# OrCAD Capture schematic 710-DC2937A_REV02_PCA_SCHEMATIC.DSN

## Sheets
1 PAGE1: company: ANALOG DEVICES; note: DEMO BOARD BILL OF MATERIALS; note: LOW EMI LOW IQ SEPIC CONVERTER
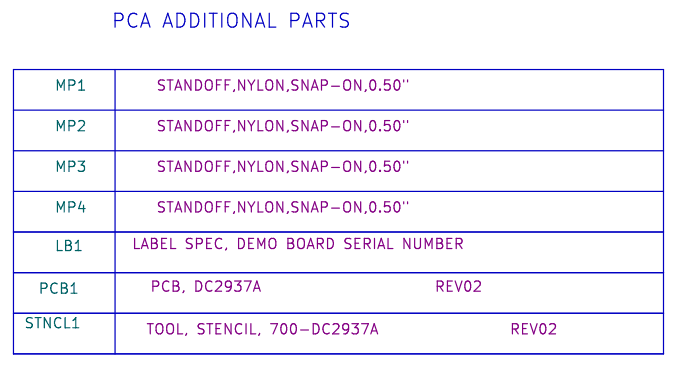
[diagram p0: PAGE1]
2 LT8357EMSE: size Custom; title: Q; note: LOW I     HIGH POWER BOOST CONVERTER
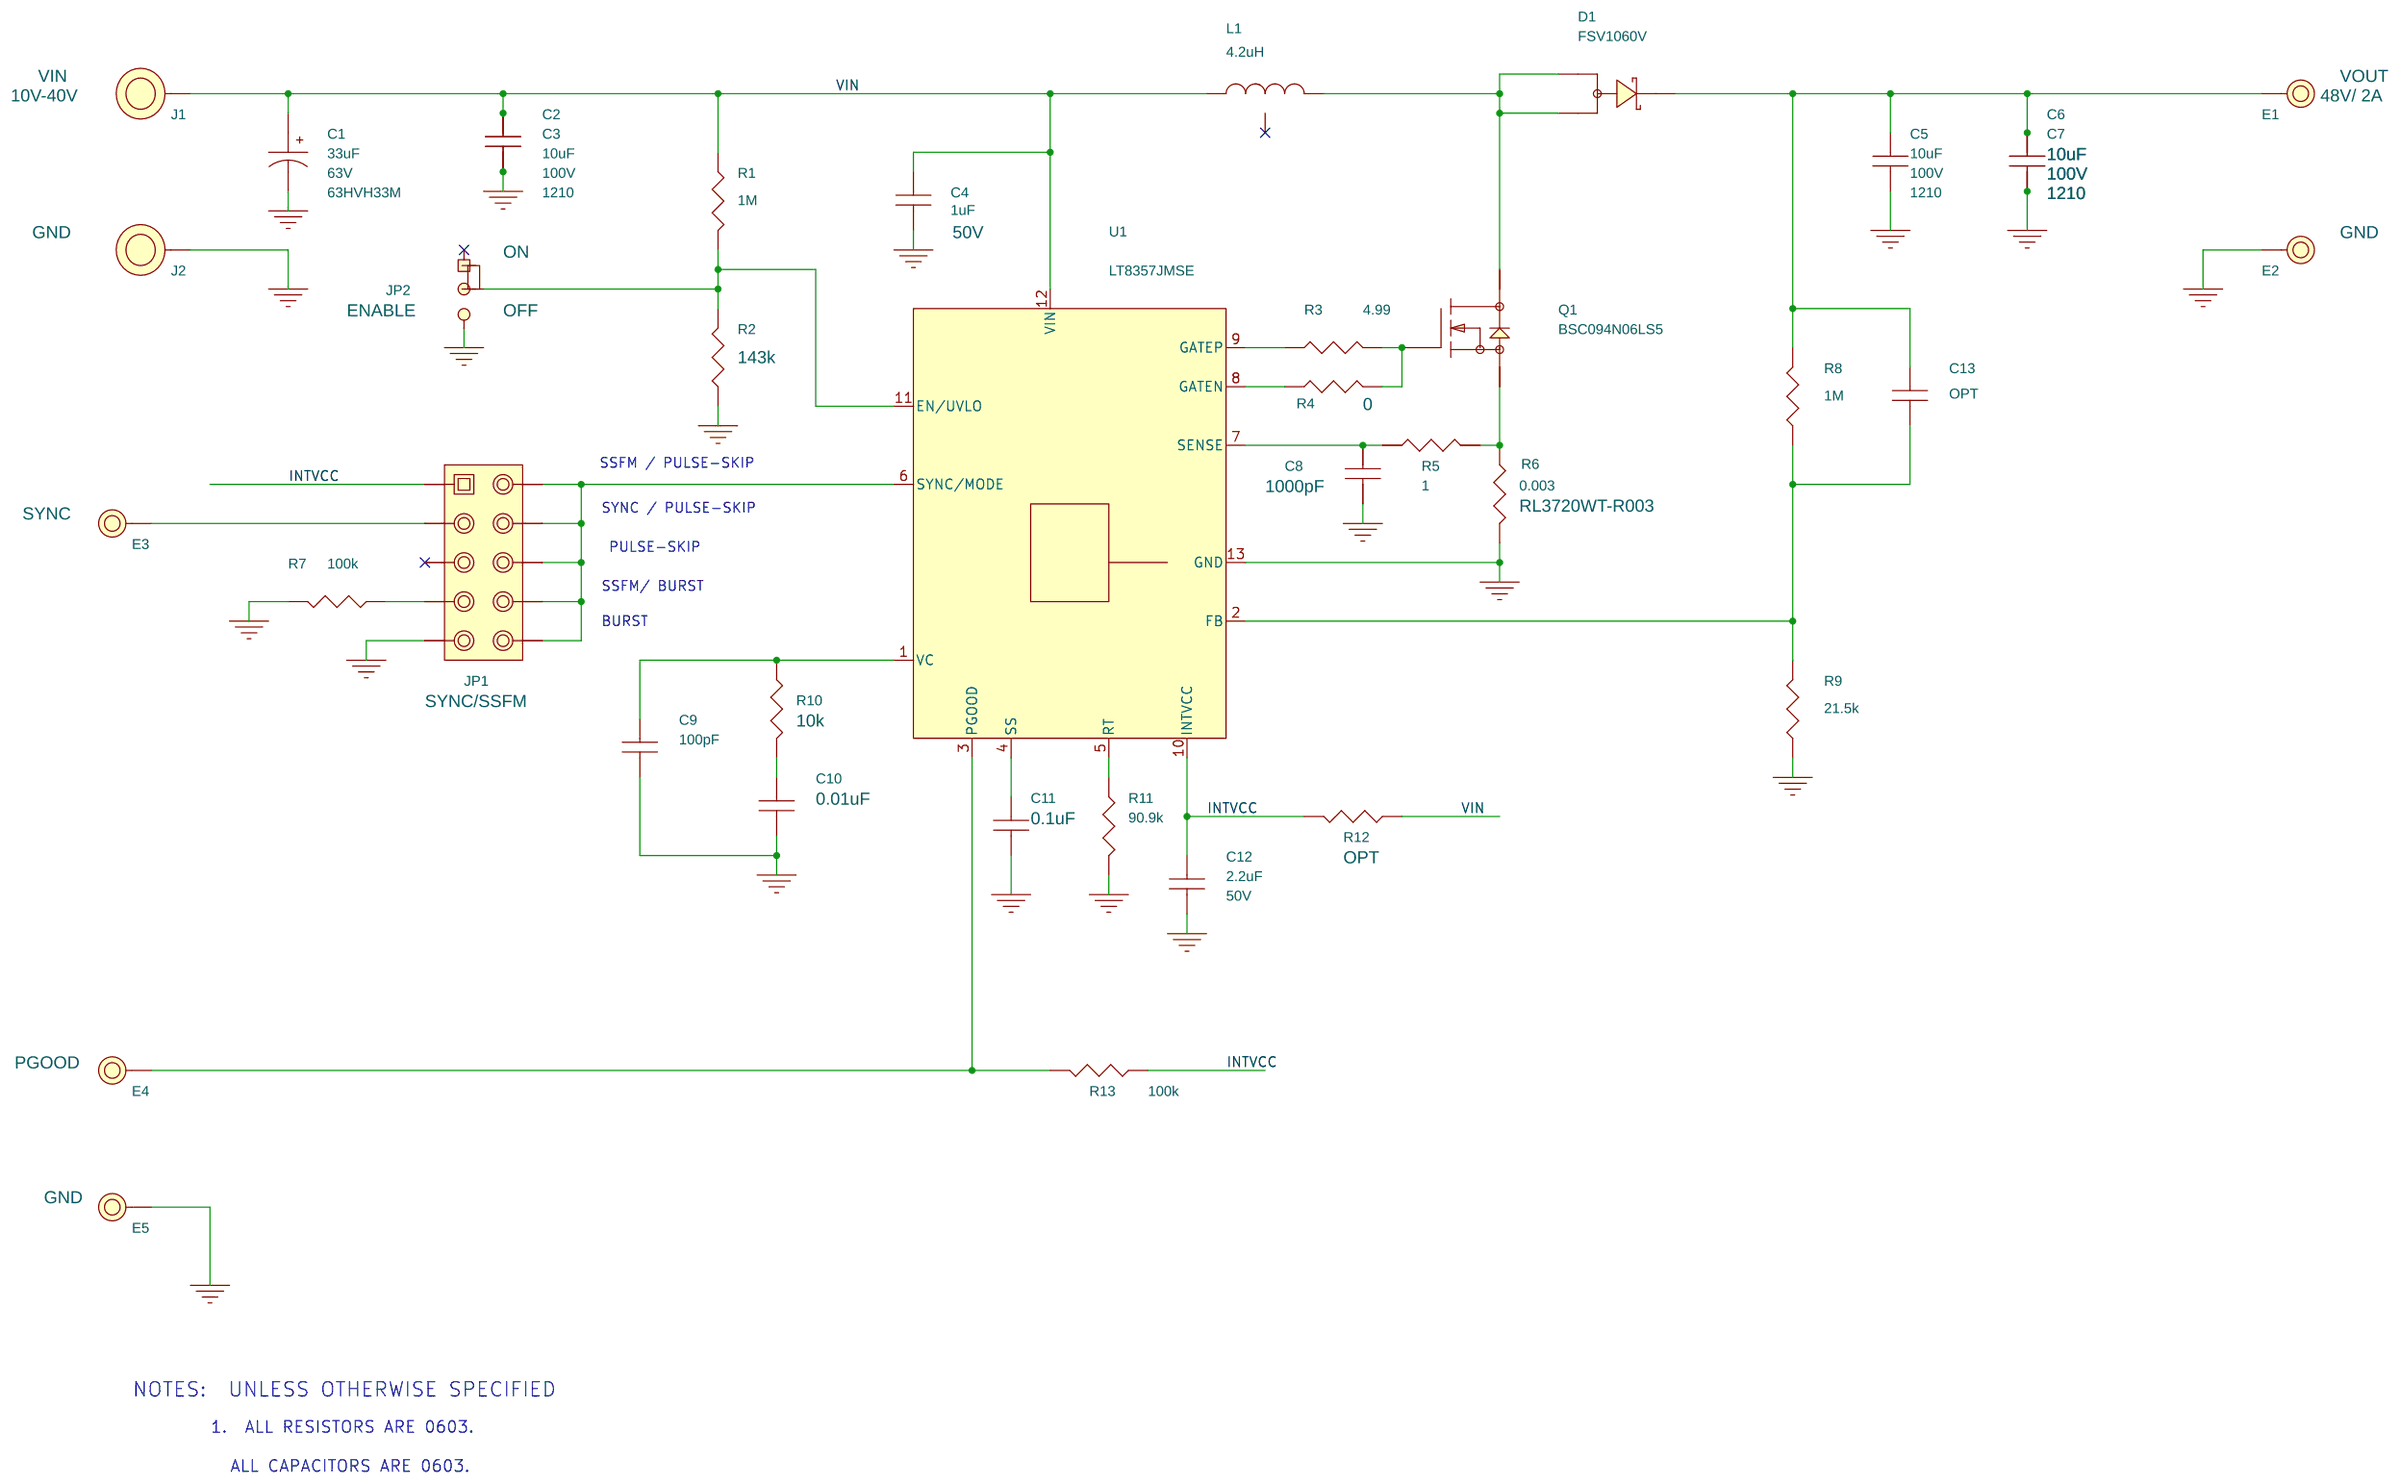
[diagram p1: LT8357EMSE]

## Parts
sheet LT8357EMSE
C1  33uF  [SUNCON_HVH_10X10.5]
C2  10uF  [CC1210N]
C3  10uF  [CC1210N]
C4  1uF  [CC0603N]
C5  10uF  [CC1210N]
C6  10uF  [CC1210N]
C7  10uF  [CC1210N]
C8  1000pF  [CC0603N]
C9  100pF  [CC0603N]
C10  0.01uF  [CC0603N]
C11  0.1uF  [CC0603N]
C12  2.2uF  [CC0603N]
C13  OPT  [CC0603N]
D1  FSV1060V  [TO-277-3N]
E1  TEST POINT  [MILLMAX2501]
E2  TEST POINT  [MILLMAX2501]
E3  TEST POINT  [MILLMAX2501]
E4  TEST POINT  [MILLMAX2501]
E5  TEST POINT  [MILLMAX2501]
J1  BANANA JACK  [KEY-575-4]
J2  BANANA JACK  [KEY-575-4]
JP1  HDR  [HD2X5-079]
JP2  HDR  [HD1X3-079]
L1  4.2uH  [WURTH-2013]
Q1  BSC094N06LS5  [INFINEON-PG-TDSON-8]
R1  1M  [CR0603N]
R2  143k  [CR0603N]
R3  4.99  [CR0603N]
R4  0  [CR0603N]
R5  1  [CR0603N]
R6  0.003  [SUSUMU-RL3720W]
R7  100k  [CR0603N]
R8  1M  [CR0603N]
R9  21.5k  [CR0603N]
R10  10k  [CR0603N]
R11  90.9k  [CR0603N]
R12  OPT  [CR0603N]
R13  100k  [CR0603N]
U1  LT8357JMSE  [LTC-MSOP-12-1666]
XJP1  SHUNT
XJP2  SHUNT
sheet PAGE1
LB1  LABEL  [895-0154_REV01]
MP1  STANDOFF  [KEYSTONE_8829-8834]
MP2  STANDOFF  [KEYSTONE_8829-8834]
MP3  STANDOFF  [KEYSTONE_8829-8834]
MP4  STANDOFF  [KEYSTONE_8829-8834]
PCB1  PCB, DC2937A
STNCL1  TOOL, STENCIL, 700-DC2937A

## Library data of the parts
C1 = CAP_P_ALT: CAP.,33uF,ALUM. ELECT.,63V,20%,10x10.5mm SMD; CLASS: DISCRETE; Dielectric Type: ALUM. ELECT.; Inventory Qty: 7004; Manufacturer: SUN ELECTRONIC INDUSTRIES CORP; Manufacturer PN: 63HVH33M; PART_NUMBER: 150-3490; Package Size: 10x10.5mm SMD; Rated Voltage: 63V; Tolerance: 20%
C2 C3 C5-C7 = CAP: CAP.,10uF,X7S,100V,10%,1210; CLASS: DISCRETE; Dielectric Type: X7S; FPLIST: CC1210N,CC1210L,CC1210M; Inventory Qty: 17323; Manufacturer: MURATA; Manufacturer PN: GRM32EC72A106KE05L; PART_NUMBER: 150-2537; Package Size: 1210; Package Type: Surface Mount, MLCC; Rated Voltage: 100V; Temperature Coefficient: X7S; Tolerance: 10%
C4 = CAP: CAP.,1uF,X7R,50V,10%,0603; CLASS: DISCRETE; Dielectric Type: X7R; FPLIST: CC0603N,CC0603L,CC0603M; Inventory Qty: 17863; Manufacturer: AVX; Manufacturer PN: 06035C105KAT2A; PART_NUMBER: 150-2333; Package Size: 0603; Rated Voltage: 50V; Tolerance: 10%
C8 = CAP: CAP.,1000pF,C0G,50V,5%,0603,AEC-Q200; CLASS: DISCRETE; Dielectric Type: C0G; FPLIST: CC0603N,CC0603L,CC0603M; Inventory Qty: 8000; Manufacturer: TDK; Manufacturer PN: CGA3E2C0G1H102J; PART_NUMBER: 150-2678; Package Size: 0603; Package Type: Surface Mount, MLCC; Rated Voltage: 50V; Temperature Coefficient: C0G, NP0; Tolerance: 5%
C9 = CAP: CAP.,100pF,C0G,50V,5%,0603,AEC-Q200; 1ST FIELD PART: TBD; CLASS: DISCRETE; Dielectric Type: C0G; FPLIST: CC0603N,CC0603L,CC0603M; Inventory Qty: 31163; Manufacturer: TDK; Manufacturer PN: CGA3E2C0G1H101J; PART_NUMBER: 150-0516; Package Size: 0603; Rated Voltage: 50V; Tolerance: 5%
C10 = CAP: CAP.,0.01uF,X7R,50V,10%,0603,AEC-Q200; 1ST FIELD PART: TBD; CLASS: DISCRETE; Dielectric Type: X7R; FPLIST: CC0603N,CC0603L,CC0603M; Inventory Qty: 1984; Manufacturer: AVX; Manufacturer PN: 06035C103K4T2A; PART_NUMBER: 150-0499; Package Size: 0603; Rated Voltage: 50V; Tolerance: 10%
C11 = CAP: CAP.,0.1uF,X7R,50V,10%,0603,AEC-Q200; 1ST FIELD PART: TBD; CLASS: DISCRETE; Dielectric Type: X7R; FPLIST: CC0603N,CC0603L,CC0603M; Inventory Qty: 20285; Manufacturer: TDK; Manufacturer PN: CGA3E2X7R1H104K; PART_NUMBER: 150-0514; Package Size: 0603; Rated Voltage: 50V; Tolerance: 10%
C12 = CAP: CAP.,2.2uF,X5R,50V,10%,0603; CLASS: DISCRETE; Dielectric Type: X5R; FPLIST: CC0603N,CC0603L,CC0603M; Inventory Qty: 35700; Manufacturer: TAIYO YUDEN; Manufacturer PN: UMK107BBJ225KA-T; PART_NUMBER: 150-0229; Package Size: 0603; Package Type: Surface Mount, MLCC; Rated Voltage: 50V; Temperature Coefficient: X5R; Tolerance: 10%
C13 = CAP: CAP., OPTION, 0603; CLASS: DISCRETE; FPLIST: CC0603N,CC0603L,CC0603M; PART_NUMBER: 150-3038; Package Size: 0603; Package Type: SMD
D1 = DIODE_SCHOTTKY_PACKAGE4: DIODE,SCHOTTKY,60V,10A,TO277-3; CLASS: DISCRETE; Inventory Qty: 0; Manufacturer: ON Semiconductor; PART_NUMBER: 210-0418; Package Size: TO-277, 3-PowerDFN; Package Type: TO277-3; Rated Voltage or Zener Voltage: 60V
E1 = TESTPOINT_.219_MILL-MAX_2501: TEST POINT,TURRET,0.094" MTG. HOLE,PCB 0.062" THK; CLASS: IO; FPLIST: MILLMAX2501,MILLMAX2501_ALT1; Inventory Qty: 609905; Manufacturer: MILL-MAX; Manufacturer PN: 2501-2-00-80-00-00-07-0; PART_NUMBER: 260-0003; Part_Field_01: VOUT; Part_Field_02: 48V/ 2A
E2 E5 = TESTPOINT_.219_MILL-MAX_2501: TEST POINT,TURRET,0.094" MTG. HOLE,PCB 0.062" THK; CLASS: IO; FPLIST: MILLMAX2501,MILLMAX2501_ALT1; Inventory Qty: 609905; Manufacturer: MILL-MAX; Manufacturer PN: 2501-2-00-80-00-00-07-0; PART_NUMBER: 260-0003; Part_Field_01: GND
E3 = TESTPOINT_.219_MILL-MAX_2501: TEST POINT,TURRET,0.094" MTG. HOLE,PCB 0.062" THK; CLASS: IO; FPLIST: MILLMAX2501,MILLMAX2501_ALT1; Inventory Qty: 609905; Manufacturer: MILL-MAX; Manufacturer PN: 2501-2-00-80-00-00-07-0; PART_NUMBER: 260-0003; Part_Field_01: SYNC
E4 = TESTPOINT_.219_MILL-MAX_2501: TEST POINT,TURRET,0.094" MTG. HOLE,PCB 0.062" THK; CLASS: IO; FPLIST: MILLMAX2501,MILLMAX2501_ALT1; Inventory Qty: 609905; Manufacturer: MILL-MAX; Manufacturer PN: 2501-2-00-80-00-00-07-0; PART_NUMBER: 260-0003; Part_Field_01: PGOOD
J1 = BANANA_KEYSTONE-575-4: CONN.,BANANA JACK,FEMALE,THT,NON-INSULATED,SWAGE,0.218"; CLASS: IO; Inventory Qty: 187327; Manufacturer: KEYSTONE; Manufacturer PN: 575-4; PART_NUMBER: 250-0428; Part_Field_01: VIN; Part_Field_02: 10V-40V
J2 = BANANA_KEYSTONE-575-4: CONN.,BANANA JACK,FEMALE,THT,NON-INSULATED,SWAGE,0.218"; CLASS: IO; Inventory Qty: 187327; Manufacturer: KEYSTONE; Manufacturer PN: 575-4; PART_NUMBER: 250-0428; Part_Field_01: GND
JP1 = HDR2X5_ALT1: CONN.,HDR,MALE,2x5,2mm,VERT,ST,THT; 1ST PART FIELD: SYNC/SSFM; CLASS: IO; Inventory Qty: 546; Manufacturer: WURTH ELEKTRONIK; Manufacturer PN: 62001021121; PART_NUMBER: 250-0679
JP2 = 1X3_D: CONN.,HDR,MALE,1x3,2mm,VERT,ST,THT,NO SUBS. ALLOWED; 1ST PART FIELD: ENABLE; 1st_Part_Field: ON; 2nd_Part_Filed: OFF; CLASS: IO; Inventory Qty: 24006; Manufacturer: Wurth Elektronik; Manufacturer PN: 62000311121; PART_NUMBER: 250-0639
L1 = IND_3PIN: IND.,4.2uH,POWER CHOKE SHEILDED,15%,24A,3.04mOHMS,2013; CLASS: DISCRETE; Inventory Qty: 700; Manufacturer: WURTH ELEKTRONIK; Manufacturer PN: 7443630420; PART_NUMBER: 200-0603; Package Size: 2013; Tolerance: 15%
Q1 = 8P_N-CH_TYPE1D: XSTR.,MOSFET,N-CHAN,60V,47A,8-pin TDSON; CLASS: DISCRETE; Inventory Qty: 4332; Manufacturer: INFINEON; Manufacturer PN: BSC094N06LS5ATMA1; PART_NUMBER: 240-0353; Package Size: 8-PowerTDFN; Package Type: 8-pin TDSON; Polarity: N-Channel; Rated Voltage: 60V
R1 R8 = RES: RES.,1M OHM,1%,1/10W,0603,AEC-Q200; CLASS: DISCRETE; FPLIST: CR0603N,CR0603L,CR0603M; Inventory Qty: 162958; Manufacturer: VISHAY; Manufacturer PN: CRCW06031M00FKEA; PART_NUMBER: 100-0335; Package Size: 0603; Rated Power: 1/10W; Temperature Coefficient: 100ppm; Tolerance: 1%
R2 = RES: RES.,143k OHMS,1%,1/10W,0603,AEC-Q200; CLASS: DISCRETE; FPLIST: CR0603N,CR0603L,CR0603M; Inventory Qty: 19828; Manufacturer: PANASONIC; Manufacturer PN: ERJ3EKF1433V; PART_NUMBER: 100-2875; Package Size: 0603; Rated Power: 1/10W; Temperature Coefficient: +/-100ppm; Tolerance: 1%
R3 = RES: RES.,4.99 OHMS,1%,1/10W,0603,AEC-Q200; CLASS: DISCRETE; FPLIST: CR0603N,CR0603L,CR0603M; Inventory Qty: 30000; Manufacturer: VISHAY; Manufacturer PN: CRCW06034R99FKEA; PART_NUMBER: 100-0521; Package Size: 0603; Rated Power: 1/10W; Temperature Coefficient: 100ppm; Tolerance: 1%
R4 = RES: RES.,0 OHM,1/10W,0603,AEC-Q200; CLASS: DISCRETE; FPLIST: CR0603N,CR0603L,CR0603M; Inventory Qty: 716853; Manufacturer: VISHAY; Manufacturer PN: CRCW06030000Z0EA; PART_NUMBER: 100-0009; Package Size: 0603; Rated Power: 1/10W
R5 = RES: RES.,1 OHM,1%,1/10W,0603,AEC-Q200; CLASS: DISCRETE; FPLIST: CR0603N,CR0603L,CR0603M; Inventory Qty: 53443; Manufacturer: NIC; Manufacturer PN: NRC06F1R00TRF; PART_NUMBER: 100-0238; Package Size: 0603; Rated Power: 1/10W; Temperature Coefficient: 100ppm/C; Tolerance: 1%
R6 = RES: RES.,0.003 OHM,1%,1W,1508 LONG-SIDE TERM; 1st_Part_Field: RL3720WT-R003; CLASS: DISCRETE; Inventory Qty: 0; Manufacturer: Susumu; Manufacturer PN: RL3720WT-R003-F; PART_NUMBER: 100-1333; Package Size: 1508 LONG-SIDE TERM; Rated Power: 1W; Temperature Coefficient: +/-350ppm; Tolerance: 1%
R7 = RES: RES.,100k OHMS,1%,1/10W,0603; CLASS: DISCRETE; FPLIST: CR0603N,CR0603L,CR0603M; Inventory Qty: 71061; Manufacturer: STACKPOLE ELECTRONICS, INC.; Manufacturer PN: RMCF0603FG100K; PART_NUMBER: 100-0112; Package Size: 0603; Rated Power: 1/10W; Tolerance: 1%
R9 = RES: RES.,21.5k OHMS,1%,1/10W,0603; CLASS: DISCRETE; FPLIST: CR0603N,CR0603L,CR0603M; Inventory Qty: 10704; Manufacturer: VISHAY; Manufacturer PN: CRCW060321K5FKEA; PART_NUMBER: 100-0107; Package Size: 0603; Rated Power: 1/10W; Temperature Coefficient: 100ppm/C; Tolerance: 1%
R10 = RES: RES.,10k OHMS,1%,1/10W,0603,AEC-Q200; 1ST FIELD PART: TBD; CLASS: DISCRETE; FPLIST: CR0603N,CR0603L,CR0603M; Inventory Qty: 161452; Manufacturer: VISHAY; Manufacturer PN: CRCW060310K0FKEA; PART_NUMBER: 100-2012; Package Size: 0603; Rated Power: 1/10W; Temperature Coefficient: +/-100ppm/C; Tolerance: 1%
R11 = RES: RES.,90.9k OHMS,1%,1/10W,0603,AEC-Q200; CLASS: DISCRETE; FPLIST: CR0603N,CR0603L,CR0603M; Inventory Qty: 76786; Manufacturer: VISHAY; Manufacturer PN: CRCW060390K9FKEA; PART_NUMBER: 100-2379; Package Size: 0603; Rated Power: 1/10W; Temperature Coefficient: 100ppm/C; Tolerance: 1%
R12 = RES: RES., OPTION, 0603; CLASS: DISCRETE; FPLIST: CR0603N,CR0603L,CR0603M; PART_NUMBER: 100-2374; Package Size: 0603
R13 = RES: RES.,100k OHMS,1%,1/10W,0603,AEC-Q200; CLASS: DISCRETE; FPLIST: CR0603N,CR0603L,CR0603M; Inventory Qty: 186177; Manufacturer: VISHAY; Manufacturer PN: CRCW0603100KFKEA; PART_NUMBER: 100-0343; Package Size: 0603; Rated Power: 1/10W; Temperature Coefficient: +/-100ppm; Tolerance: 1%
U1 = LT8357-MSE: IC,CURRENT MODE, DC/DC CONTROLLER,MSOP-12,WIDE INPUT RANGE; CLASS: IC; Inventory Qty: 0; Manufacturer: ANALOG DEVICES; Manufacturer PN: LT8357JMSE#PBF; PART_NUMBER: TMP-6534; Package Size: 12-MSOP; Package Type: MSOP-12
XJP1 = SHUNT_2MM_C: CONN.,SHUNT,FEMALE,2 POS,2mm; CLASS: IO; Inventory Qty: 67720; Manufacturer: Wurth Elektronik; Manufacturer PN: 60800213421; PART_NUMBER: 250-0485
XJP2 = SHUNT_2MM_B: CONN.,SHUNT,FEMALE,2 POS,2mm; CLASS: IO; Inventory Qty: 67720; Manufacturer: Wurth Elektronik; Manufacturer PN: 60800213421; PART_NUMBER: 250-0485
LB1 = BLANK_LABEL: LABEL SPEC, DEMO BOARD SERIAL NUMBER; Inventory Qty: 0; Manufacturer: BRADY; Manufacturer PN: THT-96-717-10; PART_NUMBER: 895-0154
MP1-MP4 = BLANK_MECHANICAL_PART: STANDOFF,NYLON,SNAP-ON,0.50"; CLASS: DISCRETE; Inventory Qty: 197954; Manufacturer: KEYSTONE; Manufacturer PN: 8833; PART_NUMBER: 763-0007
PCB1 = BLANK_PCB_PART: BOM Notes: REV02; CLASS: DISCRETE; Inventory Qty: 0; Manufacturer: EAGLE TECH. INC.; Manufacturer PN: 600-DC2937A; PART_NUMBER: 600-DC2937A
STNCL1 = BLANK_STENCIL_PART: BOM Notes: REV02; CLASS: DISCRETE; Inventory Qty: 0; Manufacturer: ANALOG DEVICES; Manufacturer PN: 830-DC2937A; PART_NUMBER: 830-DC2937A

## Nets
GND: C1.2 C2.2 C3.2 C4.2 C5.2 C6.2 C7.2 C8.2 C9.2 C10.2 C11.2 C12.2 E2.1 E5.1 J2.1 JP1.9 JP2.3 R2.1 R6.2 R7.2 R9.1 R11.2 U1.13(GND)
VIN: C1.1 C2.1 C3.1 C4.1 J1.1 L1.1 R1.1 R12.1 U1.12(VIN)
INTVCC: C12.1 JP1.1 R12.2 R13.1 U1.10(INTVCC)
N1228802: JP2.2 R1.2 R2.2 U1.11(EN/UVLO)
N1229424: JP1.2 JP1.4 JP1.6 JP1.8 JP1.10 U1.6(SYNC/MODE)
N1229562: E3.1 JP1.3
N1230153: JP1.7 R7.1
N1232161: C11.1 U1.4(SS)
N1232739: R11.1 U1.5(RT)
N1234611: D1.1 D1.2 L1.2 Q1.5(D) Q1.6(D) Q1.7(D) Q1.8(D)
N1235307: C5.1 C6.1 C7.1 C13.1 D1.3 E1.1 R8.2
N1236976: C13.2 R8.1 R9.2 U1.2(FB)
N1243361: E4.1 R13.2 U1.3(PGOOD)
N1243835: Q1.4(G) R3.2 R4.2
N1252479: C8.1 R5.1 U1.7(SENSE)
N1252486: Q1.1(S) Q1.2(S) Q1.3(S) R5.2 R6.1
N1303899: C9.1 R10.1 U1.1(VC)
N1316481: C10.1 R10.2
N1317191: R3.1 U1.9(GATEP)
N1317199: R4.1 U1.8(GATEN)

Not connected (* = marked no-connect by the designer): JP1 5*; JP2 1*; L1 3*

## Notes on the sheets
sheet 1
- PCA ADDITIONAL PARTS
sheet 2
- SSFM / PULSE-SKIP
- SYNC / PULSE-SKIP
- PULSE-SKIP
- SSFM/ BURST
- BURST
- NOTES:  UNLESS OTHERWISE SPECIFIED
- 1.  ALL RESISTORS ARE 0603.
- ALL CAPACITORS ARE 0603.
